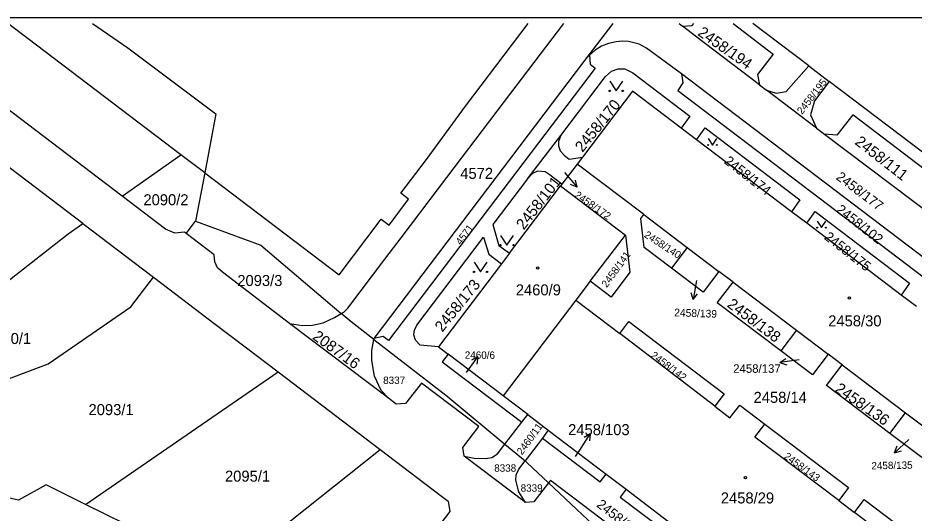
# Model space of a CAD drawing. Extents: x -606208 to -605570, y -1157873 to -1157573.
# Drawn here: x -606068.9 to -605930.7, y -1157652.8 to -1157576.5 of the extents above; entities that cross this region are included whole.
import ezdxf

# ---------------------------------------------------------------- set-up
doc = ezdxf.new("R2010")
doc.units = 0
doc.layers.add('Vrstva 1', color=7, linetype='Continuous')
doc.layers.add('Vrstva 62', color=7, linetype='Continuous')

msp = doc.modelspace()

# ---------------------------------------------------------------- linework, layer by layer
at = {"layer": 'Vrstva 1'}
msp.add_lwpolyline([(-606203.28, -1157873.46), (-605573.29, -1157873.46), (-605573.29, -1157576.47), (-606203.28, -1157576.47)], close=True, dxfattribs=at)
at = {"layer": 'Vrstva 62'}
for p, q in [((-605977.19, -1157577.34), (-605981.53, -1157583.05)), ((-605977.19, -1157577.34), (-605981.53, -1157583.05)), ((-605946.97, -1157583.87), (-605955.57, -1157577.34)), ((-605962.9, -1157580.48), (-605966.43, -1157577.72)), ((-605954.58, -1157586.77), (-605962.9, -1157580.48)), ((-605981.53, -1157583.05), (-606014.01, -1157625.89)), ((-605981.53, -1157583.05), (-605980.79, -1157582.23)), ((-605981.53, -1157583.05), (-605980.79, -1157582.23)), ((-605946.97, -1157583.87), (-605943.82, -1157586.26)), ((-605906.26, -1157630.89), (-605966.57, -1157585.11)), ((-605954.86, -1157585.21), (-605954.58, -1157586.77)), ((-605954.58, -1157586.77), (-605953.48, -1157587.6)), ((-605915.01, -1157608.14), (-605943.82, -1157586.26)), ((-605953.48, -1157587.6), (-605951.97, -1157588.08)), ((-605945.75, -1157593.44), (-605953.48, -1157587.6)), ((-605946.7, -1157591.4), (-605945.75, -1157593.44)), ((-605964.25, -1157595.24), (-605966.61, -1157593.44)), ((-605945.75, -1157593.44), (-605944.51, -1157594.38)), ((-605990.31, -1157601.28), (-605985.2, -1157594.57)), ((-605949.63, -1157606.34), (-605964.25, -1157595.24)), ((-605942.62, -1157594.56), (-605944.51, -1157594.38)), ((-606052.84, -1157603.93), (-606043.78, -1157597.57)), ((-606040.1, -1157600.37), (-606043.78, -1157597.57)), ((-605981.85, -1157597.92), (-605982.67, -1157599.01)), ((-605982.67, -1157599.01), (-605985.02, -1157602.09)), ((-606040.1, -1157600.37), (-606041.52, -1157607.82)), ((-605984.64, -1157600.32), (-605982.67, -1157602.58)), ((-605993.1, -1157612.75), (-605985.22, -1157602.36)), ((-605985.02, -1157602.09), (-605985.22, -1157602.36)), ((-605985.22, -1157602.36), (-605975.23, -1157609.94)), ((-605982.67, -1157602.58), (-605983.71, -1157602.16)), ((-605982.67, -1157602.58), (-605982.95, -1157601.5)), ((-605947.26, -1157608.13), (-605949.63, -1157606.34)), ((-606042.94, -1157609.7), (-606041.52, -1157607.82)), ((-605972.4, -1157606.78), (-605965.7, -1157611.85)), ((-606058.87, -1157608.16), (-606048, -1157616.41)), ((-605932.7, -1157619.19), (-605947.26, -1157608.13)), ((-605980.65, -1157617.07), (-605975.23, -1157609.94)), ((-605965.7, -1157611.85), (-605968.13, -1157615.03)), ((-605965.7, -1157611.85), (-605960.8, -1157615.56)), ((-605993.1, -1157612.75), (-605994.33, -1157614.36)), ((-605994.33, -1157614.36), (-606004.05, -1157627.17)), ((-605958.64, -1157617.19), (-605960.8, -1157615.56)), ((-605980.65, -1157617.07), (-605982.86, -1157619.99)), ((-605964.29, -1157616.94), (-605964.76, -1157619.9)), ((-605958.64, -1157617.19), (-605948.87, -1157624.59)), ((-605964.76, -1157619.9), (-605965.1, -1157618.84)), ((-605964.76, -1157619.9), (-605964.11, -1157618.99)), ((-605982.86, -1157619.99), (-605994.08, -1157634.74)), ((-605982.86, -1157619.99), (-605976.11, -1157625.14)), ((-605930.37, -1157620.95), (-605932.7, -1157619.19)), ((-606011.77, -1157635.08), (-606027.03, -1157623.57)), ((-605948.87, -1157624.59), (-605951.27, -1157627.79)), ((-605948.87, -1157624.59), (-605943.95, -1157628.31)), ((-606014.01, -1157625.89), (-606014.01, -1157626.05)), ((-606014.01, -1157625.89), (-606014.01, -1157626.05)), ((-605961.45, -1157636.34), (-605976.11, -1157625.14)), ((-606004.05, -1157627.17), (-606002.57, -1157628.29)), ((-605994.08, -1157634.74), (-606002.57, -1157628.29)), ((-605999.72, -1157631.15), (-605997.96, -1157628.72)), ((-605997.96, -1157628.72), (-605998.95, -1157629.24)), ((-605997.96, -1157628.72), (-605998.14, -1157629.83)), ((-605941.81, -1157629.93), (-605943.95, -1157628.31)), ((-605951.41, -1157629.57), (-605950.48, -1157628.95)), ((-605948.43, -1157629.2), (-605951.41, -1157629.57)), ((-605951.41, -1157629.57), (-605950.35, -1157629.94)), ((-605941.81, -1157629.93), (-605932.02, -1157637.34)), ((-606058.47, -1157651.46), (-606028.76, -1157631.04)), ((-606028.76, -1157631.04), (-606013.04, -1157642.98)), ((-605990.29, -1157637.62), (-605994.08, -1157634.74)), ((-605991.21, -1157638.78), (-605990.29, -1157637.62)), ((-605990.29, -1157637.62), (-605987.14, -1157640)), ((-605934.44, -1157640.52), (-605932.02, -1157637.34)), ((-605932.02, -1157637.34), (-605927.12, -1157641.05)), ((-605993.81, -1157642.18), (-605991.21, -1157638.78)), ((-605987.14, -1157640), (-605988.02, -1157641.23)), ((-605987.14, -1157640), (-605978.21, -1157646.78)), ((-605982.28, -1157643.08), (-605980.65, -1157640.56)), ((-605980.65, -1157640.56), (-605981.61, -1157641.13)), ((-605980.65, -1157640.56), (-605980.77, -1157641.68)), ((-605993.81, -1157642.18), (-605990.7, -1157644.77)), ((-605988.02, -1157641.23), (-605990.7, -1157644.77)), ((-605931.55, -1157641.46), (-605933.74, -1157643.51)), ((-605933.74, -1157643.51), (-605933.35, -1157642.46)), ((-606037, -1157662.02), (-606013.04, -1157642.98)), ((-605982.95, -1157644.1), (-605982.28, -1157643.08)), ((-605933.74, -1157643.51), (-605932.67, -1157643.19)), ((-605990.66, -1157651.15), (-606000.07, -1157644.05)), ((-605990.66, -1157651.15), (-606000.07, -1157644.05)), ((-605978.21, -1157646.78), (-605975.11, -1157649.14)), ((-605975.11, -1157649.14), (-605957.79, -1157662.29)), ((-605942.34, -1157650.87), (-605939.92, -1157652.7)), ((-606037, -1157662.02), (-606058.47, -1157651.46)), ((-605925.55, -1157663.59), (-605939.92, -1157652.7))]:
    msp.add_line(p, q, dxfattribs=at)
for points in [[(-606058.87, -1157608.16), (-606099.48, -1157577.34)], [(-606052.84, -1157603.93), (-606087.9, -1157577.34)], [(-606043.78, -1157597.57), (-606067.34, -1157579.69), (-606070.43, -1157577.34)], [(-606057.4, -1157577.34), (-606051.95, -1157581.07), (-606038.36, -1157591.24), (-606040.1, -1157600.37)], [(-606040.1, -1157600.37), (-606019.39, -1157616.09), (-606012.87, -1157607.5), (-606011.67, -1157608.41), (-606008.65, -1157604.43), (-606009.84, -1157603.51), (-606005.89, -1157598.31), (-605999.9, -1157590.06), (-605990.22, -1157577.34)], [(-606019.06, -1157622.04), (-606018.67, -1157621.81), (-606018.04, -1157621.21), (-606012.3, -1157613.65), (-606009.79, -1157610.35), (-606003.88, -1157602.56), (-605993.85, -1157589.36), (-605984.73, -1157577.34)], [(-605966.94, -1157577.34), (-605966.43, -1157577.72)], [(-605966.43, -1157577.72), (-605964.92, -1157577.65), (-605964.68, -1157577.34)], [(-605958.64, -1157577.34), (-605952.46, -1157582.07), (-605954.86, -1157585.21)], [(-605966.57, -1157585.11), (-605971.99, -1157581.13), (-605973.09, -1157580.54), (-605974.74, -1157580.09), (-605975.72, -1157580.03), (-605976.68, -1157580.14), (-605977.86, -1157580.41), (-605978.92, -1157580.83), (-605979.89, -1157581.44), (-605980.79, -1157582.23)], [(-605980.79, -1157582.23), (-605980.68, -1157583.59), (-605979.91, -1157584.24), (-606011.76, -1157626.18), (-606012.57, -1157625.58), (-606014.01, -1157625.89)], [(-605980.79, -1157582.23), (-605980.68, -1157583.59), (-605979.91, -1157584.24), (-606011.76, -1157626.18), (-606012.57, -1157625.58), (-606014.01, -1157625.89)], [(-605985.2, -1157594.57), (-605978.32, -1157585.5), (-605977.38, -1157584.66), (-605976.34, -1157584.31), (-605975.3, -1157584.33), (-605974.11, -1157584.93), (-605965.29, -1157591.61), (-605966.61, -1157593.44)], [(-605951.97, -1157588.08), (-605950.42, -1157587.81), (-605946.97, -1157583.87)], [(-605966.57, -1157585.11), (-605966.37, -1157586.46), (-605967.15, -1157587.67), (-605908.79, -1157631.94), (-605907.87, -1157630.75), (-605906.26, -1157630.89)], [(-605977.65, -1157586.22), (-605976.65, -1157587.72), (-605975.65, -1157586.22)], [(-605943.82, -1157586.26), (-605946.07, -1157589.26), (-605946.7, -1157591.4)], [(-605966.61, -1157593.44), (-605974.12, -1157587.74), (-605981.85, -1157597.92)], [(-605920.12, -1157611.51), (-605917.77, -1157608.48), (-605940.17, -1157591.39), (-605942.62, -1157594.56)], [(-605964.25, -1157595.24), (-605962.93, -1157593.41), (-605948.32, -1157604.52), (-605949.63, -1157606.34)], [(-605985.2, -1157594.57), (-605985.57, -1157595.53), (-605985.57, -1157596.21), (-605985.29, -1157596.97), (-605984.69, -1157597.65), (-605983.89, -1157598.26), (-605981.85, -1157597.92)], [(-605962.46, -1157595.05), (-605961.79, -1157596.06), (-605961.12, -1157595.05)], [(-605944.51, -1157594.38), (-605920.34, -1157612.64), (-605920.04, -1157612.86)], [(-605972.4, -1157606.78), (-605972.67, -1157606.58), (-605982.67, -1157599.01)], [(-605985.02, -1157602.09), (-605986.97, -1157600.59), (-605987.59, -1157600.22), (-605988.81, -1157600.11), (-605989.58, -1157600.46), (-605990.31, -1157601.28)], [(-605990.31, -1157601.28), (-605995.67, -1157608.34), (-605994.73, -1157611.57), (-605993.1, -1157612.75)], [(-606042.94, -1157609.7), (-606043.22, -1157609.49), (-606044.72, -1157609.67), (-606046.13, -1157609.02), (-606052.84, -1157603.93)], [(-605947.26, -1157608.13), (-605945.95, -1157606.31), (-605931.41, -1157617.34), (-605932.7, -1157619.19)], [(-606041.52, -1157607.82), (-606031.43, -1157611.52), (-606019.06, -1157622.04)], [(-605968.13, -1157615.03), (-605972.35, -1157611.85), (-605972.86, -1157607.39), (-605972.4, -1157606.78)], [(-605945.67, -1157607.78), (-605945, -1157608.79), (-605944.33, -1157607.78)], [(-606076.16, -1157621.45), (-606061.16, -1157609.77), (-606058.87, -1157608.16)], [(-606027.03, -1157623.57), (-606037.38, -1157615.67), (-606038.11, -1157614.98), (-606038.56, -1157614.05), (-606038.64, -1157613), (-606042.94, -1157609.7)], [(-606004.05, -1157627.17), (-606006.9, -1157626.91), (-606007.58, -1157626.17), (-606007.85, -1157625.31), (-606007.77, -1157624.58), (-606007.38, -1157623.82), (-605997.12, -1157610.25), (-605996.28, -1157612.91), (-605994.33, -1157614.36)], [(-605994.49, -1157609.99), (-605993.49, -1157611.49), (-605992.49, -1157609.99)], [(-605975.23, -1157609.94), (-605974.53, -1157615.67), (-605977.43, -1157619.52), (-605980.65, -1157617.07)], [(-605998.56, -1157614.13), (-605997.56, -1157615.63), (-605996.56, -1157614.13)], [(-605960.8, -1157615.56), (-605963.22, -1157618.74), (-605968.13, -1157615.03)], [(-606088.05, -1157646.56), (-606080.19, -1157635.82), (-606064.22, -1157629.8), (-606051.47, -1157621.02), (-606048, -1157616.41)], [(-606048, -1157616.41), (-606044.55, -1157619.03), (-606038.68, -1157623.5), (-606033.64, -1157627.32), (-606028.76, -1157631.04)], [(-605951.27, -1157627.79), (-605961.07, -1157620.39), (-605958.64, -1157617.19)], [(-606027.03, -1157623.57), (-606025.02, -1157623.91), (-606023.48, -1157623.84), (-606021.83, -1157623.45), (-606020.11, -1157622.66), (-606019.06, -1157622.04)], [(-606014.01, -1157626.05), (-606017.54, -1157623.33), (-606019.06, -1157622.04)], [(-605976.11, -1157625.14), (-605974.69, -1157623.26), (-605959.98, -1157634.4), (-605961.45, -1157636.34)], [(-606011.77, -1157635.08), (-606012.87, -1157633.92), (-606013.91, -1157631.7), (-606014.32, -1157629.28), (-606014.32, -1157627.76), (-606014.01, -1157626.05)], [(-606011.77, -1157635.08), (-606012.87, -1157633.92), (-606013.91, -1157631.7), (-606014.32, -1157629.28), (-606014.32, -1157627.76), (-606014.01, -1157626.05)], [(-606014.01, -1157626.05), (-606002.69, -1157634.76), (-605993.81, -1157642.18)], [(-606002.57, -1157628.29), (-606003.5, -1157629.47), (-605991.21, -1157638.78)], [(-605943.95, -1157628.31), (-605946.37, -1157631.5), (-605951.27, -1157627.79)], [(-605934.44, -1157640.52), (-605944.21, -1157633.13), (-605941.81, -1157629.93)], [(-606000.07, -1157644.05), (-606000.29, -1157642.68), (-605997.83, -1157639.45), (-606006.66, -1157632.76), (-606009.15, -1157635.92), (-606010.59, -1157636), (-606011.77, -1157635.08)], [(-606000.07, -1157644.05), (-606000.29, -1157642.68), (-605997.83, -1157639.45), (-606006.66, -1157632.76), (-606009.15, -1157635.92), (-606010.59, -1157636), (-606011.77, -1157635.08)], [(-605961.45, -1157636.34), (-605959.11, -1157638.13), (-605957.59, -1157636.16), (-605953.74, -1157639.08)], [(-605942.34, -1157650.87), (-605955.25, -1157641.08), (-605953.74, -1157639.08)], [(-605953.74, -1157639.08), (-605940.85, -1157648.88), (-605942.34, -1157650.87)], [(-605927.12, -1157641.05), (-605929.53, -1157644.24), (-605934.44, -1157640.52)], [(-606000.07, -1157644.05), (-605998.53, -1157644.34), (-605996.78, -1157644.38), (-605995.81, -1157644.22), (-605994.97, -1157643.69), (-605993.81, -1157642.18)], [(-605988.02, -1157641.23), (-605979.13, -1157647.96), (-605978.21, -1157646.78)], [(-606013.04, -1157642.98), (-606003.58, -1157650.18), (-606002.55, -1157650.96), (-606002.31, -1157652.57), (-606003.64, -1157654.29), (-606002.66, -1157655.04)], [(-605990.66, -1157651.15), (-605991.64, -1157649.55), (-605992.15, -1157647.75), (-605992.08, -1157646.91), (-605991.65, -1157646.02), (-605990.7, -1157644.77)], [(-605990.7, -1157644.77), (-605990.37, -1157645.05), (-605987.07, -1157648.16)], [(-606058.47, -1157651.46), (-606064.55, -1157648.46), (-606068.82, -1157650.81), (-606088.05, -1157646.56)], [(-605971.61, -1157663.49), (-605969.59, -1157660.76), (-605977.24, -1157655.02), (-605986.78, -1157647.79), (-605987.07, -1157648.16)], [(-605987.07, -1157648.16), (-605989.33, -1157651.06), (-605990.66, -1157651.15)], [(-605987.07, -1157648.16), (-605989.33, -1157651.06), (-605990.66, -1157651.15)], [(-605971.61, -1157663.49), (-605977.59, -1157657.1), (-605987.07, -1157648.16)], [(-605971.61, -1157663.49), (-605977.59, -1157657.1), (-605987.07, -1157648.16)], [(-605975.11, -1157649.14), (-605976.05, -1157650.34), (-605958.73, -1157663.41), (-605957.79, -1157662.29)], [(-605939.92, -1157652.7), (-605938.41, -1157650.71), (-605923.95, -1157661.67)]]:
    msp.add_lwpolyline(points, dxfattribs=at)
for centre, radius in [((-605977.65, -1157587.72), 0.1), ((-605975.65, -1157587.72), 0.1), ((-605962.46, -1157596.06), 0.067), ((-605961.12, -1157596.06), 0.067), ((-605945.67, -1157608.79), 0.067), ((-605944.33, -1157608.79), 0.067), ((-605994.49, -1157611.49), 0.1), ((-605992.49, -1157611.49), 0.1), ((-605988.74, -1157615), 0.175), ((-605998.56, -1157615.63), 0.1), ((-605996.56, -1157615.63), 0.1), ((-605940.7, -1157619.65), 0.175), ((-605956.72, -1157647.35), 0.175)]:
    msp.add_circle(centre, radius, dxfattribs=at)

# ---------------------------------------------------------------- texts
for s, height, rotation, p in [('2458/194', 1.7, 325, (-605964.21, -1157579.05)), ('2458/195', 1.14, 52, (-605947.99, -1157591.42)), ('2458/170', 1.7, 51, (-605981.84, -1157597.28)), ('2458/111', 1.7, 322, (-605939.97, -1157595.83)), ('2458/174', 1.5, 322, (-605960.12, -1157598.78)), ('2458/101', 1.7, 52, (-605990.89, -1157609.24)), ('2458/177', 1.5, 323, (-605942.87, -1157601.24)), ('2458/172', 1.139, 325, (-605983.18, -1157604.01)), ('2458/102', 1.5, 322, (-605942.85, -1157606.27)), ('4571', 1.139, 53, (-606000.6, -1157611.57)), ('2458/140', 1.139, 327, (-605972.44, -1157610.18)), ('2458/175', 1.5, 322, (-605944.7, -1157610.47)), ('2458/141', 1.139, 54, (-605978.1, -1157618.12)), ('2458/173', 1.7, 51, (-606003.46, -1157625)), ('2458/138', 1.7, 323, (-605959.68, -1157620.9)), ('2458/139', 1.182, 358, (-605967.72, -1157622.46)), ('2087/16', 1.7, 324, (-606023.6, -1157625.87)), ('2458/142', 1.139, 323, (-605971.43, -1157628.7)), ('2458/136', 1.7, 325, (-605943.06, -1157633.97)), ('2460/11', 1.139, 54, (-605991.16, -1157643.92)), ('2458/143', 1.139, 324, (-605950.89, -1157644.28)), ('2458/135', 1.139, 1, (-605937.29, -1157646.07)), ('2458/176', 1.5, 322, (-605979.79, -1157651.72))]:
    msp.add_text(s, height=height, rotation=rotation, dxfattribs=at).set_placement(p)
for s, height, p in [('4572', 1.7, (-606000.69, -1157601.28)), ('2090/2', 1.7, (-606049.55, -1157605.35)), ('2093/3', 1.7, (-606035.07, -1157617.8)), ('2460/9', 1.7, (-605992.13, -1157619.24)), ('2458/30', 1.7, (-605943.96, -1157624.02)), ('2090/1', 1.7, (-606073.81, -1157626.74)), ('2460/6', 1.139, (-606000, -1157629.02)), ('2458/137', 1.313, (-605958.61, -1157631.18)), ('8337', 1.139, (-606012.58, -1157632.9)), ('2458/14', 1.7, (-605955.47, -1157635.81)), ('2093/1', 1.7, (-606058.01, -1157637.7)), ('2458/103', 1.7, (-605984.06, -1157640.79)), ('8338', 1.139, (-605995.46, -1157646.43)), ('2095/1', 1.7, (-606036.97, -1157647.96)), ('8339', 1.139, (-605991.38, -1157649.51)), ('2458/29', 1.7, (-605960.52, -1157651.32))]:
    msp.add_text(s, height=height, dxfattribs=at).set_placement(p)

doc.saveas('drawing.dxf')
